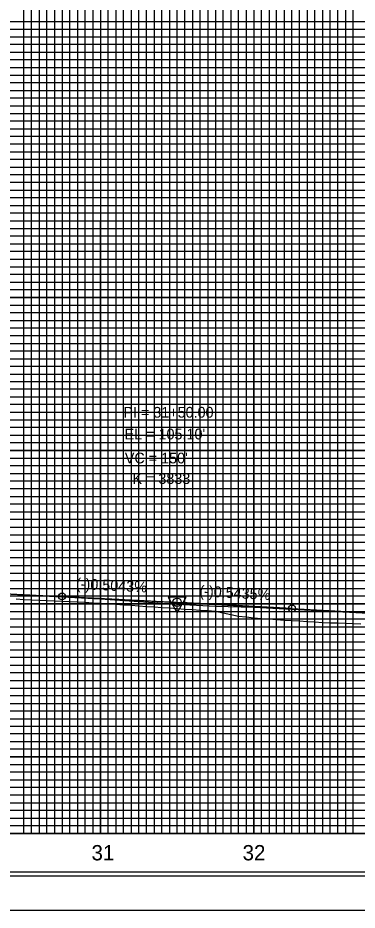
# Model space of a CAD drawing. Extents: x 2345490 to 2436403, y 465165 to 573888.
# Drawn here: x 2383813 to 2384034, y 515088 to 515670 of the extents above; entities that cross this region are included whole.
import ezdxf

# ---------------------------------------------------------------- set-up
doc = ezdxf.new("R2010")
doc.units = 0
for name, color, linetype in [('Old_Level_1', 7, 'Continuous'), ('Old_Level_18', 7, 'Continuous'), ('Old_Level_2', 7, 'Continuous'), ('Old_Level_41', 7, 'Continuous'), ('Old_Level_42', 7, 'Continuous'), ('Old_Level_43', 7, 'Continuous'), ('Old_Level_50', 7, 'Continuous'), ('Old_Level_51', 7, 'Continuous'), ('Old_Level_57', 7, 'Continuous'), ('Old_Level_61', 7, 'Continuous'), ('Old_Level_62', 7, 'Continuous'), ('Old_Level_63', 7, 'Continuous')]:
    doc.layers.add(name, color=color, linetype=linetype)

msp = doc.modelspace()

# ---------------------------------------------------------------- linework, layer by layer
at = {"layer": 'Old_Level_1'}
msp.add_lwpolyline([(2383811.799, 515290.6575), (2383816.799, 515290.41675), (2383821.799, 515290.18175), (2383826.799, 515289.94125), (2383831.799, 515289.70075), (2383836.799, 515289.46025), (2383841.799, 515289.2195), (2383846.799, 515288.979), (2383851.799, 515288.741), (2383856.799, 515288.5005), (2383861.799, 515288.2445), (2383866.799, 515287.899), (2383871.799, 515287.55325), (2383876.799, 515287.2075), (2383881.799, 515286.86175), (2383886.799, 515286.516), (2383891.799, 515286.166), (2383896.799, 515285.82025), (2383901.799, 515285.4745), (2383906.799, 515285.129), (2383911.799, 515284.78325), (2383916.799, 515284.4375), (2383921.799, 515284.086), (2383926.799, 515283.739), (2383931.799, 515283.39325), (2383936.799, 515283.0475), (2383941.799, 515282.696), (2383946.799, 515281.57175), (2383951.799, 515280.44725), (2383956.799, 515279.42225), (2383961.799, 515278.9305), (2383966.799, 515278.43875), (2383971.799, 515277.9825), (2383976.799, 515277.6345), (2383981.799, 515277.2865), (2383986.799, 515276.9385), (2383991.799, 515276.5905), (2383996.799, 515276.311), (2384001.799, 515276.0205), (2384006.799, 515275.6725), (2384011.799, 515275.35725), (2384016.799, 515275.1515), (2384021.799, 515274.99275), (2384026.799, 515274.83375), (2384031.799, 515274.675), (2384036.799, 515274.44575)], dxfattribs=at)
at = {"layer": 'Old_Level_18'}
msp.add_lwpolyline([(2384616.79875, 516162.5265), (2383116.79875, 516162.5265), (2383116.79875, 515112.5265), (2384616.79875, 515112.5265)], close=True, dxfattribs=at)
at = {"layer": 'Old_Level_2'}
for p, q in [((2383796.799, 515294.57875), (2383841.799, 515292.30925)), ((2383841.799, 515292.30925), (2383914.0525, 515288.66525)), ((2383991.799, 515284.4505), (2383919.545, 515288.3775)), ((2383991.799, 515284.4505), (2384076.799, 515279.831))]:
    msp.add_line(p, q, dxfattribs=at)
msp.add_lwpolyline([(2383922.72475, 515291.811), (2383910.98225, 515291.7965), (2383916.86575, 515281.67825)], close=True, dxfattribs=at)
for centre, radius in [((2383841.799, 515292.30925), 2.25), ((2383916.799, 515288.5265), 2.75), ((2383916.799, 515288.5265), 2.75), ((2383991.799, 515284.4505), 2.25)]:
    msp.add_circle(centre, radius, dxfattribs=at)
msp.add_spline([(2383841.799, 515292.30925), (2383844.799, 515292.15775), (2383847.799, 515292.00625), (2383850.799, 515291.85425), (2383853.799, 515291.70225), (2383856.799, 515291.54975), (2383859.799, 515291.39725), (2383862.799, 515291.24425), (2383865.799, 515291.09125), (2383868.799, 515290.938), (2383871.799, 515290.7845), (2383874.799, 515290.63075), (2383877.799, 515290.47675), (2383880.799, 515290.3225), (2383883.799, 515290.168), (2383886.799, 515290.01325), (2383889.799, 515289.85825), (2383892.799, 515289.70325), (2383895.799, 515289.54775), (2383898.799, 515289.392), (2383901.799, 515289.23625), (2383904.799, 515289.08), (2383907.799, 515288.92375), (2383910.799, 515288.76725), (2383913.799, 515288.61025), (2383916.799, 515288.45325), (2383919.799, 515288.296), (2383922.799, 515288.1385), (2383925.799, 515287.98075), (2383928.799, 515287.82275), (2383931.799, 515287.6645), (2383934.799, 515287.506), (2383937.799, 515287.34725), (2383940.799, 515287.18825), (2383943.799, 515287.02925), (2383946.799, 515286.86975), (2383949.799, 515286.71025), (2383952.799, 515286.55025), (2383955.799, 515286.39025), (2383958.799, 515286.22975), (2383961.799, 515286.06925), (2383964.799, 515285.9085), (2383967.799, 515285.74725), (2383970.799, 515285.586), (2383973.799, 515285.4245), (2383976.799, 515285.26275), (2383979.799, 515285.10075), (2383982.799, 515284.9385), (2383985.799, 515284.77625), (2383988.799, 515284.6135), (2383991.799, 515284.4505)], degree=3, dxfattribs=at)
at = {"layer": 'Old_Level_41'}
msp.add_line((2384616.79875, 515137.5265), (2383116.79875, 515137.5265), dxfattribs=at)
for points in [[(2383766.79875, 515137.5265), (2383816.79875, 515137.5265), (2383816.79875, 516162.5265)], [(2383841.79875, 516162.5265), (2383841.79875, 515137.5265), (2383891.79875, 515137.5265), (2383891.79875, 516162.5265)], [(2383866.79875, 516162.5265), (2383866.79875, 515137.5265), (2383916.79875, 515137.5265), (2383916.79875, 516162.5265)], [(2383941.79875, 516162.5265), (2383941.79875, 515137.5265), (2383991.79875, 515137.5265), (2383991.79875, 516162.5265)], [(2383966.79875, 516162.5265), (2383966.79875, 515137.5265), (2384016.79875, 515137.5265), (2384016.79875, 516162.5265)], [(2384616.79875, 515662.5265), (2383116.79875, 515662.5265), (2383116.79875, 515612.5265), (2384616.79875, 515612.5265)], [(2384616.79875, 515562.5265), (2383116.79875, 515562.5265), (2383116.79875, 515512.5265), (2384616.79875, 515512.5265)], [(2384616.79875, 515487.5265), (2383116.79875, 515487.5265), (2383116.79875, 515537.5265), (2384616.79875, 515537.5265)], [(2384616.79875, 515462.5265), (2383116.79875, 515462.5265), (2383116.79875, 515412.5265), (2384616.79875, 515412.5265)], [(2384616.79875, 515387.5265), (2383116.79875, 515387.5265), (2383116.79875, 515437.5265), (2384616.79875, 515437.5265)], [(2384616.79875, 515362.5265), (2383116.79875, 515362.5265), (2383116.79875, 515312.5265), (2384616.79875, 515312.5265)], [(2384616.79875, 515262.5265), (2383116.79875, 515262.5265), (2383116.79875, 515212.5265), (2384616.79875, 515212.5265)], [(2384616.79875, 515187.5265), (2383116.79875, 515187.5265), (2383116.79875, 515237.5265), (2384616.79875, 515237.5265)], [(2384616.79875, 515162.5265), (2383116.79875, 515162.5265)]]:
    msp.add_lwpolyline(points, dxfattribs=at)
at = {"layer": 'Old_Level_42'}
for points in [[(2384616.79875, 515587.5265), (2383116.79875, 515587.5265), (2383116.79875, 515637.5265), (2384616.79875, 515637.5265)], [(2384616.79875, 515287.5265), (2383116.79875, 515287.5265), (2383116.79875, 515337.5265), (2384616.79875, 515337.5265)]]:
    msp.add_lwpolyline(points, dxfattribs=at)
at = {"layer": 'Old_Level_43'}
for points in [[(2383811.79875, 515137.5265), (2383821.79875, 515137.5265), (2383821.79875, 516162.5265), (2383826.79875, 516162.5265), (2383826.79875, 515137.5265), (2383831.79875, 515137.5265), (2383831.79875, 516162.5265), (2383836.79875, 516162.5265), (2383836.79875, 515137.5265), (2383846.79875, 515137.5265), (2383846.79875, 516162.5265), (2383851.79875, 516162.5265), (2383851.79875, 515137.5265), (2383856.79875, 515137.5265), (2383856.79875, 516162.5265), (2383861.79875, 516162.5265), (2383861.79875, 515137.5265), (2383871.79875, 515137.5265), (2383871.79875, 516162.5265), (2383876.79875, 516162.5265), (2383876.79875, 515137.5265)], [(2383876.79875, 515137.5265), (2383881.79875, 515137.5265), (2383881.79875, 516161.9265)], [(2383886.79875, 516161.9265), (2383886.79875, 515137.5265), (2383896.79875, 515137.5265), (2383896.79875, 516162.5265)], [(2383901.79875, 516162.5265), (2383901.79875, 515137.5265), (2383906.79875, 515137.5265), (2383906.79875, 516162.5265)], [(2383911.79875, 516162.5265), (2383911.79875, 515137.5265), (2383921.79875, 515137.5265), (2383921.79875, 516162.5265)], [(2383926.79875, 516162.5265), (2383926.79875, 515137.5265), (2383931.79875, 515137.5265), (2383931.79875, 516162.5265)], [(2383936.79875, 516162.5265), (2383936.79875, 515137.5265), (2383946.79875, 515137.5265), (2383946.79875, 516162.5265)], [(2383951.79875, 516162.5265), (2383951.79875, 515137.5265), (2383956.79875, 515137.5265), (2383956.79875, 516162.5265)], [(2383961.79875, 516162.5265), (2383961.79875, 515137.5265), (2383971.79875, 515137.5265), (2383971.79875, 516162.5265)], [(2383976.79875, 516162.5265), (2383976.79875, 515137.5265), (2383981.79875, 515137.5265), (2383981.79875, 516162.5265)], [(2383986.79875, 516162.5265), (2383986.79875, 515137.5265), (2383996.79875, 515137.5265), (2383996.79875, 516162.5265)], [(2384001.79875, 516162.5265), (2384001.79875, 515137.5265), (2384006.79875, 515137.5265), (2384006.79875, 516162.5265)], [(2384011.79875, 516162.5265), (2384011.79875, 515137.5265), (2384021.79875, 515137.5265), (2384021.79875, 516162.5265)], [(2384026.79875, 516162.5265), (2384026.79875, 515137.5265), (2384031.79875, 515137.5265), (2384031.79875, 516162.5265)], [(2384566.79875, 515667.5265), (2383166.79875, 515667.5265), (2383166.79875, 515657.5265), (2384566.79875, 515657.5265)], [(2384566.79875, 515652.5265), (2383166.79875, 515652.5265), (2383166.79875, 515647.5265), (2384566.79875, 515647.5265)], [(2384566.79875, 515642.5265), (2383166.79875, 515642.5265)], [(2383166.79875, 515632.5265), (2384566.79875, 515632.5265)], [(2384566.79875, 515627.5265), (2383166.79875, 515627.5265), (2383166.79875, 515622.5265), (2384566.79875, 515622.5265)], [(2384566.79875, 515617.5265), (2383166.79875, 515617.5265), (2383166.79875, 515607.5265), (2384566.79875, 515607.5265)], [(2384566.79875, 515602.5265), (2383166.79875, 515602.5265), (2383166.79875, 515597.5265), (2384566.79875, 515597.5265)], [(2384566.79875, 515592.5265), (2383166.79875, 515592.5265), (2383166.79875, 515582.5265), (2384566.79875, 515582.5265)], [(2384566.79875, 515577.5265), (2383166.79875, 515577.5265), (2383166.79875, 515572.5265), (2384566.79875, 515572.5265)], [(2384566.79875, 515567.5265), (2383166.79875, 515567.5265), (2383166.79875, 515557.5265), (2384566.79875, 515557.5265)], [(2384566.79875, 515552.5265), (2383166.79875, 515552.5265), (2383166.79875, 515547.5265), (2384566.79875, 515547.5265)], [(2384566.79875, 515542.5265), (2383166.79875, 515542.5265), (2383166.79875, 515532.5265), (2384566.79875, 515532.5265)], [(2384566.79875, 515527.5265), (2383166.79875, 515527.5265), (2383166.79875, 515522.5265), (2384566.79875, 515522.5265)], [(2384566.79875, 515517.5265), (2383166.79875, 515517.5265), (2383166.79875, 515507.5265), (2384566.79875, 515507.5265)], [(2384566.79875, 515502.5265), (2383166.79875, 515502.5265), (2383166.79875, 515497.5265), (2384566.79875, 515497.5265)], [(2384566.79875, 515492.5265), (2383166.79875, 515492.5265), (2383166.79875, 515482.5265), (2384566.79875, 515482.5265)], [(2384566.79875, 515477.5265), (2383166.79875, 515477.5265), (2383166.79875, 515472.5265), (2384566.79875, 515472.5265)], [(2384566.79875, 515467.5265), (2383166.79875, 515467.5265), (2383166.79875, 515457.5265), (2384566.79875, 515457.5265)], [(2384566.79875, 515452.5265), (2383166.79875, 515452.5265), (2383166.79875, 515447.5265), (2384566.79875, 515447.5265)], [(2384566.79875, 515442.5265), (2383166.79875, 515442.5265), (2383166.79875, 515432.5265), (2384566.79875, 515432.5265)], [(2384566.79875, 515427.5265), (2383166.79875, 515427.5265), (2383166.79875, 515422.5265), (2384566.79875, 515422.5265)], [(2384566.79875, 515417.5265), (2383166.79875, 515417.5265), (2383166.79875, 515407.5265), (2384566.79875, 515407.5265)], [(2384566.79875, 515402.5265), (2383166.79875, 515402.5265), (2383166.79875, 515397.5265), (2384566.79875, 515397.5265)], [(2384566.79875, 515392.5265), (2383166.79875, 515392.5265), (2383166.79875, 515382.5265), (2384566.79875, 515382.5265)], [(2384566.79875, 515377.5265), (2383166.79875, 515377.5265), (2383166.79875, 515372.5265), (2384566.79875, 515372.5265)], [(2384566.79875, 515367.5265), (2383166.79875, 515367.5265), (2383166.79875, 515357.5265), (2384566.79875, 515357.5265)], [(2384566.79875, 515352.5265), (2383166.79875, 515352.5265), (2383166.79875, 515347.5265), (2384566.79875, 515347.5265)], [(2384566.79875, 515342.5265), (2383166.79875, 515342.5265)], [(2383166.79875, 515332.5265), (2384566.79875, 515332.5265)], [(2384566.79875, 515327.5265), (2383166.79875, 515327.5265), (2383166.79875, 515322.5265), (2384566.79875, 515322.5265)], [(2384566.79875, 515317.5265), (2383166.79875, 515317.5265)], [(2383166.79875, 515307.5265), (2384566.79875, 515307.5265)], [(2384566.79875, 515302.5265), (2383166.79875, 515302.5265), (2383166.79875, 515297.5265), (2384566.79875, 515297.5265)], [(2384566.79875, 515292.5265), (2383166.79875, 515292.5265), (2383166.79875, 515282.5265), (2384566.79875, 515282.5265)], [(2384566.79875, 515277.5265), (2383166.79875, 515277.5265), (2383166.79875, 515272.5265), (2384566.79875, 515272.5265)], [(2384566.79875, 515267.5265), (2383166.79875, 515267.5265), (2383166.79875, 515257.5265), (2384566.79875, 515257.5265)], [(2384566.79875, 515252.5265), (2383166.79875, 515252.5265), (2383166.79875, 515247.5265), (2384566.79875, 515247.5265)], [(2384566.79875, 515242.5265), (2383166.79875, 515242.5265), (2383166.79875, 515232.5265), (2384566.79875, 515232.5265)], [(2384566.79875, 515227.5265), (2383166.79875, 515227.5265), (2383166.79875, 515222.5265), (2384566.79875, 515222.5265)], [(2384566.79875, 515217.5265), (2383166.79875, 515217.5265), (2383166.79875, 515207.5265), (2384566.79875, 515207.5265)], [(2384566.79875, 515202.5265), (2383166.79875, 515202.5265), (2383166.79875, 515197.5265), (2384566.79875, 515197.5265)], [(2384566.79875, 515192.5265), (2383166.79875, 515192.5265), (2383166.79875, 515182.5265), (2384566.79875, 515182.5265)], [(2384566.79875, 515177.5265), (2383166.79875, 515177.5265), (2383166.79875, 515172.5265), (2384566.79875, 515172.5265)], [(2384566.79875, 515167.5265), (2383166.79875, 515167.5265), (2383166.79875, 515157.5265), (2384566.79875, 515157.5265)], [(2384566.79875, 515152.5265), (2383166.79875, 515152.5265), (2383166.79875, 515147.5265), (2384566.79875, 515147.5265)], [(2384566.79875, 515142.5265), (2383166.79875, 515142.5265)]]:
    msp.add_lwpolyline(points, dxfattribs=at)
at = {"layer": 'Old_Level_50'}
msp.add_lwpolyline([(2384629.29875, 516165.0765), (2382962.79875, 516165.0765), (2382962.79875, 515109.9765), (2384629.29875, 515109.9765)], close=True, dxfattribs=at)
at = {"layer": 'Old_Level_51'}
msp.add_lwpolyline([(2384633.79875, 516187.5265), (2382949.79875, 516187.5265), (2382949.79875, 515087.5265), (2384633.79875, 515087.5265)], close=True, dxfattribs=at)
at = {"layer": 'Old_Level_57'}
for p, q in [((2381716.79925, 515537.52675), (2386366.79875, 515537.52675)), ((2383866.79875, 515137.52675), (2383866.79875, 515537.52675)), ((2383866.79875, 515137.62675), (2383866.79875, 515537.52675)), ((2383966.79875, 515137.52675), (2383966.79875, 515537.52675)), ((2383966.79875, 515137.62675), (2383966.79875, 515537.52675)), ((2381716.79925, 515487.52675), (2386366.79875, 515487.52675)), ((2381716.79925, 515437.52675), (2386366.79875, 515437.52675)), ((2381716.79925, 515387.52675), (2386366.79875, 515387.52675)), ((2381716.79925, 515337.52675), (2386366.79875, 515337.52675)), ((2381716.79925, 515287.52675), (2386366.79875, 515287.52675)), ((2381716.79925, 515237.52675), (2386366.79875, 515237.52675)), ((2381716.799, 515187.52675), (2386366.79875, 515187.52675)), ((2381716.79925, 515137.52675), (2386366.79875, 515137.52675))]:
    msp.add_line(p, q, dxfattribs=at)
at = {"layer": 'Old_Level_61'}
msp.add_lwpolyline([(2383791.799, 515294.58775), (2383816.799, 515293.29325), (2383841.799, 515292.095), (2383866.799, 515290.776), (2383891.799, 515289.05375), (2383916.799, 515287.33175), (2383941.799, 515286.05325), (2383966.799, 515285.36025), (2383991.799, 515283.97725), (2384016.799, 515282.61625), (2384041.799, 515281.37825)], dxfattribs=at)
at = {"layer": 'Old_Level_63'}
msp.add_line((2381766.79875, 515137.5265), (2386228.05125, 515137.5265), dxfattribs=at)

# ---------------------------------------------------------------- texts
at = {"layer": 'Old_Level_2'}
for s, height, p in [('PI = 31+50.00', 7.0000005, (2383881.799, 515409.035)), ("EL = 105.10'", 7.0000005, (2383882.6295, 515394.84875)), ("VC = 150'", 7.000001, (2383882.7575, 515379.16875)), ('K = 3833', 7.000001, (2383887.73925, 515365.76125))]:
    msp.add_text(s, height=height, dxfattribs=at).set_placement(p)
for s, rotation, p in [('(-)0.5043%', 357.11274722, (2383850.74475, 515297.259)), ('(-)0.5435%', 356.88915833, (2383931.24125, 515292.4775))]:
    msp.add_text(s, height=7.000001, rotation=rotation, dxfattribs=at).set_placement(p)
at = {"layer": 'Old_Level_62'}
for s, p in [('31', (2383861.025, 515120.0265)), ('32', (2383959.57325, 515120.0265))]:
    msp.add_text(s, height=10.000001, dxfattribs=at).set_placement(p)

doc.saveas('drawing.dxf')
